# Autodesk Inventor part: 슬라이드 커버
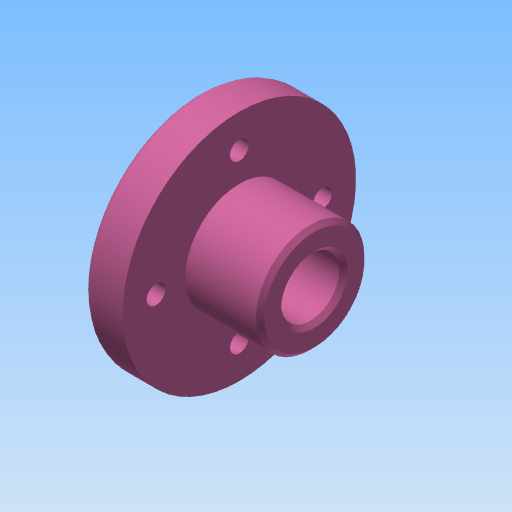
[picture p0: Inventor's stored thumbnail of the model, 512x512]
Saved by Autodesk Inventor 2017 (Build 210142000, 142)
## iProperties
Created: 2015-12
Part Number: 슬라이드 커버
Document SubType Name: Modeling
Designer: mdu
Density: 2.71 g/cm^3
Material: 알루미늄 6061
Mass: 76.471 g
Surface Area: 93.8237 cm^2
Volume: 28.2181 cm^3
Appearance: 분홍색
Author: mdu
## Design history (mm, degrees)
sketch "스케치1"
  geometry: L1 (-14, 0)-(14, 0); L2 (-14, 0)-(-14, 28); L3 (-14, 28)-(-4, 28); L4 (-4, 28)-(-4, 13); L5 (-4, 13)-(14, 13); L6 (14, 13)-(14, 0); 2 further points
  constraints: 12 end point, 3 perpendicular, 1 coincident, 1 horizontal, 1 midpoint, 1 parallel
  dimensions: "d1" = 56 diameter of L3 L1; "d2" = 26 diameter of L5 L1; "d5" = 10 distance of L2.end L3.end; "d32" = 18 distance of L4.end L5.end
revolve "회전1" sketch "스케치1" stored, may be unused: angle "d6" = 90 deg
sketch "스케치2" dims "d33" = 40
  geometry: 3 further points
  constraints: 2 vertical alignment, 1 coincident, 2 other
hole "구멍1" sketch "스케치2" at (0, 20) diameter "d8" = 4.5; stored, may be unused: countersink angle "d12" = 90 deg, drill point angle "d14" = 118 deg; dims "d9" = 6, "d10" = 8, "d11" = 4.4, "d13" = 8
hole "구멍2" diameter "d20" = 14; stored, may be unused: countersink angle "d24" = 90 deg, drill point angle "d26" = 0 deg; dims "d18" = 10, "d19" = 10, "d21" = 6, "d22" = 8, "d23" = 4.4, "d25" = 8
fillet "모깎기1" dims "d27" = 3
chamfer "모따기1" distance "d29" = 1; stored, may be unused: second distance "d30" = 2, angle "d31" = 45 deg
node "솔리드1"
pattern_circular "원형 패턴1" dims angle "d16" = 360 deg
